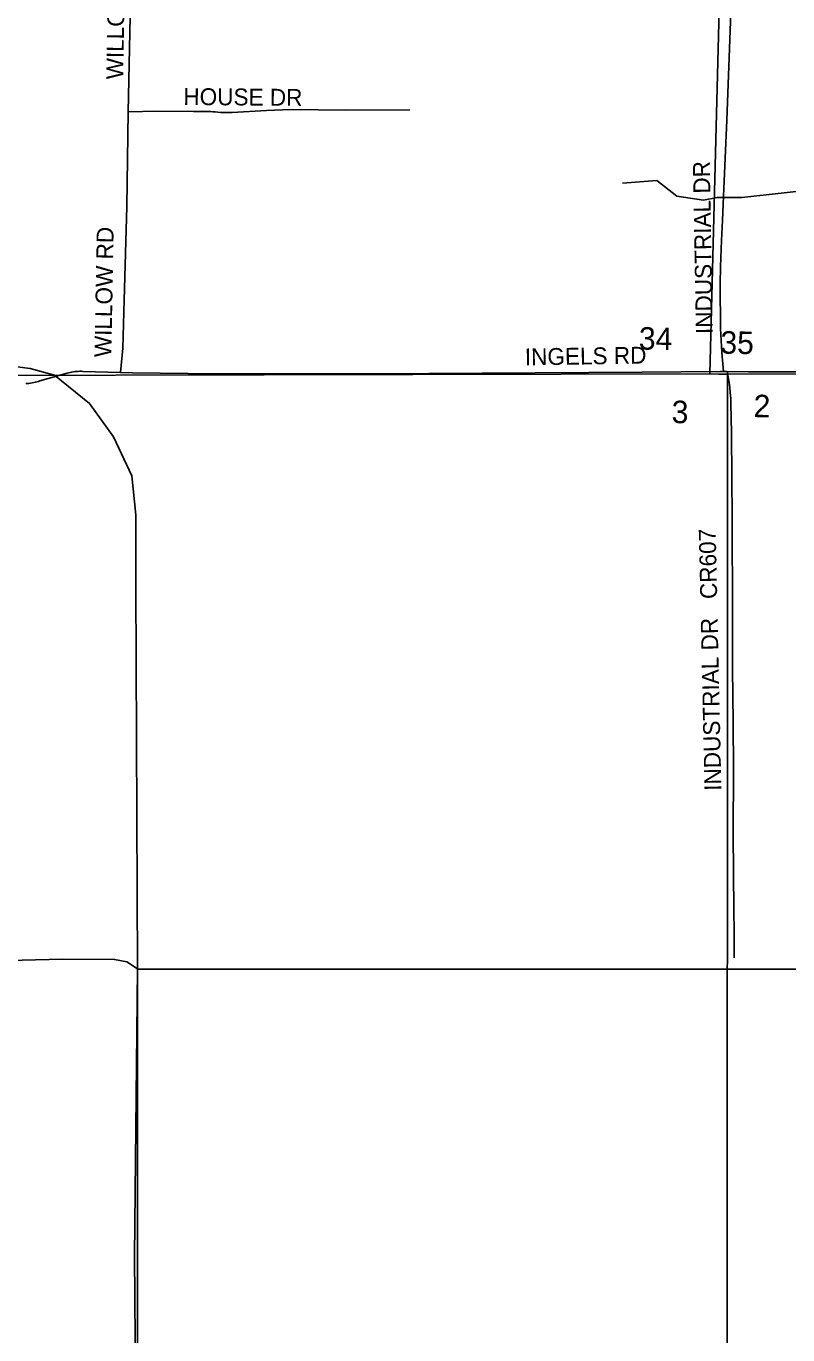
# Model space of a CAD drawing. Extents: x 1670563 to 1761545, y 515755 to 578944.
# Drawn here: x 1711727 to 1715113, y 529450 to 535267 of the extents above; entities that cross this region are included whole.
import ezdxf

# ---------------------------------------------------------------- set-up
doc = ezdxf.new("R2010")
doc.units = 0
for name, color, linetype in [('4_TwnRge', 7, 'Continuous'), ('5_sectionlines', 7, 'Continuous'), ('62_text', 7, 'Continuous'), ('LIMITS', 7, 'Continuous'), ('SHP_LINE', 7, 'Continuous'), ('STREETCL', 7, 'Continuous'), ('STRNAMES', 7, 'Continuous')]:
    doc.layers.add(name, color=color, linetype=linetype)

# ---------------------------------------------------------------- blocks, each defined once
blk = doc.blocks.new('CITY_LIMITS02')
at = {"layer": 'LIMITS'}
for points in [[(1712222, 531076.3), (1712222.8, 523168.3)], [(1718933.6, 531075.7), (1712222, 531076.3)]]:
    blk.add_lwpolyline(points, dxfattribs=at)

msp = doc.modelspace()

# ---------------------------------------------------------------- linework, layer by layer
at = {"layer": '4_TwnRge'}
for points in [[(1714766.6, 533721.4), (1720083.7, 533721.1), (1720133.6, 533723.3), (1725191.1, 533766.2)], [(1708368.8, 533698.9), (1709482.2, 533710.3), (1714766.6, 533721.4), (1714844.4, 533719.3)]]:
    msp.add_lwpolyline(points, dxfattribs=at)
at = {"layer": '5_sectionlines'}
msp.add_line((1714833, 536331), (1714766.6, 533721.4), dxfattribs=at)
msp.add_lwpolyline([(1714844.4, 533719.3), (1714842.3, 528473.5), (1714834.2, 523147.7), (1714849.9, 517839.3)], dxfattribs=at)
at = {"layer": 'SHP_LINE'}
for points in [[(1714377, 534570), (1714531, 534582), (1714619, 534511), (1714737, 534494), (1714799, 534506), (1714908, 534506), (1715258, 534544), (1715747, 534553), (1716128, 534550)], [(1708583, 534390), (1708738, 534348), (1708761, 534252), (1708898, 534067), (1709119, 533908), (1709386, 533790), (1709597, 533760), (1710030, 533749), (1710888, 533760), (1711546, 533771), (1711745, 533745), (1711853, 533716), (1712008, 533590), (1712115, 533442), (1712197, 533268), (1712215, 533095), (1712215, 532781), (1712222, 531077)], [(1712222, 531077), (1712174, 531108), (1712120, 531119), (1711889, 531120), (1711107, 531101), (1710911, 531090), (1710800, 531101), (1709598, 531094)], [(1712222, 531077), (1712208, 529802), (1712219, 528498), (1712212, 528425)]]:
    msp.add_lwpolyline(points, dxfattribs=at)
at = {"layer": 'STREETCL'}
for points in [[(1714826.7, 533731.9), (1714819, 533816.9), (1714814, 533924.1), (1714811.9, 534120.3), (1714812.6, 534198.3), (1714817.6, 534315.1), (1714821.5, 534403.1), (1714826.5, 534511.3), (1714841.5, 534849), (1714856.8, 535248.4), (1714871.3, 535647.8), (1714881.9, 536048), (1714891.8, 536446.7), (1714901, 536868.2), (1714909.4, 537287.4), (1714917.8, 537705.1), (1714924.6, 538130.4), (1714931.6, 538515.9), (1714933, 538897.9), (1714934.7, 539010.1)], [(1712181, 534886.6), (1712189.4, 535310.4), (1712193.8, 535578.9)], [(1712146.3, 533727.5), (1712156.6, 533835.8), (1712161.9, 534049.5), (1712174.1, 534466.3), (1712181, 534886.6)], [(1712181, 534886.6), (1712309.8, 534889), (1712470.3, 534888), (1712525.5, 534888.3), (1712535.9, 534888.2), (1712546.2, 534887.8), (1712556.6, 534887), (1712566.9, 534885.9), (1712579.6, 534884.5), (1712592.3, 534883.5), (1712605, 534883), (1712617.8, 534882.9), (1712630.6, 534883.2), (1712643.3, 534884), (1712795.4, 534892.9), (1712901.2, 534896.7), (1713147.5, 534893.3), (1713431.7, 534896)], [(1711724.8, 533678.7), (1711731.9, 533679), (1711739.1, 533679.7), (1711746.2, 533680.5), (1711753.2, 533681.6), (1711760.3, 533683), (1711767.2, 533684.5), (1711774.2, 533686.4), (1711781, 533688.4), (1711787.8, 533690.7), (1711908.7, 533724.8), (1711915.6, 533726.6), (1711922.6, 533728.2), (1711929.6, 533729.6), (1711936.7, 533730.7), (1711943.8, 533731.7), (1711950.9, 533732.4), (1711958, 533732.9), (1711965.1, 533733.1), (1711972.3, 533733.1), (1711979.4, 533732.9), (1712146.3, 533727.5)], [(1712146.3, 533727.5), (1712199.2, 533725.8), (1712570.5, 533722.2), (1713042, 533721.2), (1713516.7, 533723.7), (1713989.3, 533726.8), (1714464.9, 533729.4), (1714812.4, 533731.9), (1714826.7, 533731.9)], [(1714826.7, 533731.9), (1714842.3, 533731.8)], [(1714874.5, 531126.5), (1714873.8, 531242.6), (1714872.4, 531337.9), (1714870.2, 531673.7), (1714871, 531966), (1714870.2, 532171.5), (1714866.4, 532410.6), (1714866.5, 532651.8), (1714865, 533084.9), (1714864.2, 533260.3), (1714861.9, 533457.7), (1714859.4, 533590.4), (1714858.6, 533614.2), (1714856.9, 533637.9), (1714854.5, 533661.5), (1714851.2, 533685.1), (1714847.2, 533708.5), (1714842.3, 533731.8)], [(1714842.3, 533731.8), (1714937.6, 533731.4), (1715194.9, 533730.4)]]:
    msp.add_lwpolyline(points, dxfattribs=at)

# ---------------------------------------------------------------- block references
msp.add_blockref('CITY_LIMITS02', (0, 0), dxfattribs=at)

# ---------------------------------------------------------------- texts
at = {"layer": '62_text'}
for s, rotation, p in [('34', 358.93281, (1714449.7, 533830.1)), ('35', 358.93281, (1714812, 533812.1)), ('2', 358.93284, (1714959.6, 533529.6)), ('3', 358.93284, (1714595.4, 533503.2))]:
    msp.add_text(s, height=100, rotation=rotation, dxfattribs=at).set_placement(p)
at = {"layer": 'STRNAMES'}
for s, rotation, p in [('WILLOW RD', 88.94715, (1712157.7, 535030)), ('HOUSE DR', 359.5484, (1712425.4, 534917)), ('INDUSTRIAL DR', 91, (1714779.1, 533899.4)), ('WILLOW RD', 88.94715, (1712105.4, 533795.3)), ('INGELS RD', 0.90223, (1713944, 533759.3)), ('INDUSTRIAL DR   CR607', 91.26673, (1714817.4, 531869.4))]:
    msp.add_text(s, height=75, rotation=rotation, dxfattribs=at).set_placement(p)

doc.saveas('drawing.dxf')
